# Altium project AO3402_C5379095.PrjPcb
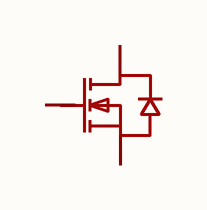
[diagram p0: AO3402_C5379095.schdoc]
1 sheet, 1 parts. Net scope: global (net labels, ports and power ports of the same name join across sheets).

## Sheet AO3402_C5379095.schdoc
size 127 x 101 mm

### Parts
Q?  ao3402_c5379095  [SOT-23-3_L2.9-W1.6-P1.90-LS2.8-BR]  (value not drawn)

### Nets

Not connected (* = marked no-connect by the designer): Q? 1(G) 2(S) 3(D)

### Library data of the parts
Q? = ao3402_c5379095: 数量:1个N沟道;漏源电压(Vdss):30V;连续漏极电流(Id):4A;导通电阻(RDS(on)):47mΩ@4.5V;耗散功率(Pd):1.4W;阈值电压(Vgs(th)):900mV;; Manufacturer: MSKSEMI(美森科); ManufacturerPart: AO3402; AddInBom: yes; ModelId: 89cb27a44ab2466697082bb9fd73a7d0; ModelName: SOT-23-3L_L2.9-W1.6-H1.1-LS2.8-P0.95; ModelTransform: 114.173,110.236,0,90,0,0,0,0,0; Number: 1个N沟道; Drain to Source Voltage: 30V; Current - Continuous Drain(Id): 4A; Pd - Power Dissipation: 1.4W; Gate Threshold Voltage (Vgs(th)): 900mV; Gate Charge(Qg): 8.4nC@4.5V; Input Capacitance(Ciss): 695pF; Reverse Transfer Capacitance (Crss@Vds): 36pF; Output Capacitance(Coss): 45pF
